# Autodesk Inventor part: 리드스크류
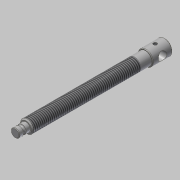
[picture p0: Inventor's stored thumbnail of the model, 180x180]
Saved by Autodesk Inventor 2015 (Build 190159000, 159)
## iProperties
Created: 2019-04
Part Number: 리드스크류
Material: 강철, 연강
Document SubType Name: Modeling
Designer: mduedu
Density: 1 g/cm^3
Appearance: 강철
Author: mduedu
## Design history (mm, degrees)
sketch "스케치1"
  geometry: C1 r 6 at (0, 0); 1 further point
  constraints: 1 centre point, 1 coincident
  dimensions: "d0" = 12 diameter of C1
extrude "돌출1" new body sketch "스케치1" distance "d1" = 110; taper "d2" = 0 deg
sketch "스케치2"
  geometry: C1 r 4 at (0, 0); 1 further point
  constraints: 1 centre point, 1 coincident
  dimensions: "d3" = 8 diameter of C1
extrude "돌출2" join sketch "스케치2" distance "d4" = 10; taper "d5" = 0 deg
sketch "스케치3"
  geometry: C1 r 7 at (0, 0); 1 further point
  constraints: 1 centre point, 1 coincident
  dimensions: "d9" = 14 diameter of C1
extrude "돌출3" join sketch "스케치3" distance "d10" = 18; taper "d11" = 0 deg
feature "스레드1" dims "d12" = 100, "d13" = 0
chamfer "모따기2" distance "d14" = 1; stored, may be unused: second distance "d15" = 2, angle "d16" = 45 deg
chamfer "모따기3" distance "d17" = 0.5; stored, may be unused: second distance "d18" = 2, angle "d19" = 45 deg
chamfer "모따기4" distance "d20" = 0.5; stored, may be unused: second distance "d21" = 2, angle "d22" = 45 deg
sketch "스케치4"
  geometry: L1 (-110, -5)-(-110, 5) reference; L2 (-119.5, 4)-(-119.5, -4) reference; L3 (-119.5, 0)-(-110, 0); C1 r 1.25 at (-115, 4); 1 further point
  constraints: 2 end point, 2 midpoint, 1 centre point
  dimensions: "d23" = 2.5 diameter of C1; "d24" = 5 distance from line of C1.centre L1; "d25" = 4 distance from line of C1.centre L3
revolve "회전1" sketch "스케치4" stored, may be unused: angle "d26" = 90 deg
sketch "스케치5"
  geometry: L1 (0, -6.5)-(0, 6.5) reference; C1 r 4 at (9, 0); 2 further points
  constraints: 1 centre point, 1 horizontal alignment, 1 midpoint
  dimensions: "d27" = 8 diameter of C1; "d28" = 9 distance from line of C1.centre L1
extrude "돌출4" cut sketch "스케치5" stored distance "d29" = 15; taper "d30" = 0 deg
node "작업 평면1"
sketch "스케치6"
  geometry: L1 (0, 6.5)-(0, -6.5) reference; 2 further points
  constraints: 1 horizontal alignment
  dimensions: "d31" = 9 distance from line of point (-9, 0) L1
hole "구멍1" sketch "스케치6" at (-9, 0) diameter "d32" = 3.242; stored, may be unused: countersink angle "d36" = 90 deg, drill point angle "d38" = 118 deg; dims "d33" = 6, "d34" = 4, "d35" = 2, "d37" = 8
node "솔리드1"
